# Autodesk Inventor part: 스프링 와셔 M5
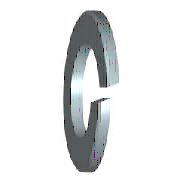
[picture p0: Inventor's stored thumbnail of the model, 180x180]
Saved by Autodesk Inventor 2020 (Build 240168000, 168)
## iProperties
IsCustomPart: 1
Created: 2012-02
Part Number: 스프링 와셔 M5
Material: 강철, 연강
Description: 스프링 와셔
Document SubType Name: Modeling
Standard: JIS B 1251
Designer: mdu-01
Standards Organization: JIS
Language: ko-KR
Size Designation: 번호 2 5
Categories: <MemberInstance><Categories><Category DisplayName="조임쇠" InternalName="e4da775c-781d-43d5-af7c-5136215cf5a6" Mnemonic="FSTN"><Category DisplayName="와셔" InternalN
Density: 1 g/cm^3
Appearance: 강철
Author: mdu-01
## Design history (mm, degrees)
sketch "스케치1"
  geometry: C1 r 4.6 at (0, 0); C2 r 2.55 at (0, 0); 1 further point
  constraints: 2 centre point, 2 coincident
  dimensions: "d0" = 5.1 diameter of C2 (= SD1); "d1" = 9.2 diameter of C1 (= SD2)
extrude "본체" new body sketch "스케치1" distance "d2" = 1.3 (= SD); taper "d3" = 0 deg
sketch "스케치2"
  geometry: L1 (0, -2.55)-(0, 2.55) reference; L2 (1.3, 4.6)-(1.3, -4.6) reference; L3 (-1.2, 0)-(7.2, 0) reference; L4 (0, -0.26)-(1.3, 0.213); L5 (0, 0.26)-(1.3, 0.733)
  constraints: 4 end point, 4 point on line, 1 parallel
  dimensions: "d4" = 0.26 distance from line of L3 L4.start (= 0.2 x SD); "d5" = 0.26 distance from line of L3 L5.start (= 0.2 x SD); "d6" = 70 deg angle of L2 L4 (= FAWI)
extrude "절단부" cut sketch "스케치2" stored distance "d7" = 1.3 (= SD); taper "d8" = 0 deg
workaxis "Work Axis1"
workplane "Work Plane1"
body "Solid1"
other parameters: "SD1" = 5.1 [user parameter; used in 1 equation term], "SD2" = 9.2 [user parameter; used in 1 equation term], "SD" = 1.3 [user parameter; used in 4 equation terms], "FAWI" = 70 deg [user parameter; used in 1 equation term], "d9" = 0, "d10" = 0, "d11" = 0, "d12" = 0, "SDI" = 1.7 [user parameter], "NND" = 5 [user parameter]
